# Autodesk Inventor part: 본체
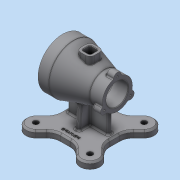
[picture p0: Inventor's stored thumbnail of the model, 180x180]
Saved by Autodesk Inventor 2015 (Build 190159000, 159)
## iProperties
Created: 2018-03
Part Number: 본체
Material: 일반
Document SubType Name: Modeling
Designer: SCD-A03
Density: 1 g/cm^3
Appearance: 기본값
Author: SCD-A03
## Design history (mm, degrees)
sketch "스케치1"
  geometry: L1 (50, 0)-(50, 45); L2 (50, 45)-(30, 45); L3 (30, 45)-(-27, 27.5); L4 (-50, 0)-(-50, 27.5); L5 (-27, 27.5)-(-50, 27.5); L6 (50, 0)-(-50, 0); L7 (0, 0)-(0, 7.405)
  constraints: 14 end point, 3 vertical, 2 horizontal, 1 perpendicular, 1 other
  dimensions: "d0" = 45 distance of L1.start L1.end; "d1" = 20 distance of L1.end L2.end; "d10" = 27.5 distance of L4.start L4.end; "d11" = 77 distance from line of L3.end L1; "d12" = 100 distance from line of L4.end L1; "d13" = 45 distance from line of L7.start L2; "d14" = 37.59532 distance from line of L7.end L2
revolve "회전1" sketch "스케치1" stored, may be unused: angle "d15" = 90 deg
node "작업 평면1"
sketch "스케치2"
  geometry: L1 (-19.544, 45)-(19.544, 45); L2 (45, 19.544)-(45, -19.544); L3 (-36.77, -36.77)-(-45, -45); L4 (-62.225, -36.77)-(-45, -19.544); L5 (19.544, 45)-(36.77, 62.225); L6 (-36.77, -62.225)-(-19.544, -45); L7 (45, 19.544)-(62.225, 36.77); L8 (45, 45)-(57.655, 57.655); L9 (-45, -45)-(-45, -32.068); L10 (-45, -19.544)-(-45, 19.544); L11 (-32.068, -45)-(-45, -45); L12 (62.225, -36.77)-(45, -19.544); L13 (-19.544, 45)-(-36.77, 62.225); L14 (45, -45)-(36.77, -36.77); L15 (-49.497, 49.497)-(-57.655, 57.655); L16 (36.77, -62.225)-(19.544, -45); L17 (-45, 19.544)-(-62.225, 36.77); L18 (-36.77, -36.77)-(-49.497, -49.497); L19 (-45, -45)-(-36.77, -36.77); L20 (45, -45)-(32.068, -45); L21 (19.544, -45)-(-19.544, -45); A1 r 18 centre (49.497, 49.497) between (62.225, 36.77) and (36.77, 62.225); A2 r 18 centre (49.497, -49.497) between (36.77, -62.225) and (62.225, -36.77); A3 r 18 centre (-49.497, 49.497) between (-36.77, 62.225) and (-62.225, 36.77); A4 r 18 centre (-49.497, -49.497) between (-62.225, -36.77) and (-36.77, -62.225); 1 further point
  constraints: 42 end point, 21 parallel, 8 point on circle, 4 centre point, 3 point on line, 1 coincident, 1 horizontal, 1 perpendicular
  dimensions: "d17" = 90 distance of L14.start L3.end; "d18" = 90 distance of L8.start L14.start; "d20" = 36 diameter of A1; "d25" = 36 diameter of A2
extrude "돌출1" join sketch "스케치2" distance "d28" = 12; taper "d29" = 0 deg
node "작업 평면2"
sketch "스케치3"
  geometry: L1 (-12.5, 12.5)-(12.5, 12.5); L2 (12.5, 12.5)-(12.5, -12.5); L3 (12.5, -12.5)-(-12.5, -12.5); L4 (-12.5, -12.5)-(-12.5, 12.5); L5 (-12.5, 12.5)-(12.5, -12.5); L6 (12.5, 12.5)-(-12.5, -12.5); 1 further point
  constraints: 12 end point, 2 midpoint, 2 parallel, 1 horizontal, 1 perpendicular
  dimensions: "d31" = 25 distance of L2.end L3.end; "d32" = 25 distance of L1.end L2.end
extrude "돌출2" join sketch "스케치3" stored distance "d33" = 12; taper "d34" = 0 deg
sketch "스케치4"
  geometry: L1 (-7.5, 7.5)-(7.5, 7.5); L2 (7.5, 7.5)-(7.5, -7.5); L3 (7.5, -7.5)-(-7.5, -7.5); L4 (-7.5, -7.5)-(-7.5, 7.5); L5 (-7.5, 7.5)-(7.5, -7.5); L6 (7.5, 7.5)-(-7.5, -7.5); 1 further point
  constraints: 12 end point, 2 midpoint, 2 parallel, 1 horizontal, 1 perpendicular
  dimensions: "d35" = 15 distance of L2.end L3.end; "d36" = 15 distance of L1.end L2.end
extrude "돌출3" cut sketch "스케치4" distance "d37" = 30; taper "d38" = 0 deg
sketch "스케치5"
  geometry: L1 (37, 4)-(-37, 4); L2 (-37, 4)-(-37, -4); L3 (-37, -4)-(37, -4); L4 (37, -4)-(37, 4); L5 (37, 4)-(-37, -4); L6 (-37, 4)-(37, -4); L7 (4, -24)-(-4, -24); L8 (-4, -24)-(-4, 24); L9 (-4, 24)-(4, 24); L10 (4, 24)-(4, -24); L11 (4, -24)-(-4, 24); L12 (-4, -24)-(4, 24); 1 further point
  constraints: 24 end point, 4 midpoint, 4 parallel, 2 horizontal, 2 perpendicular
  dimensions: "d39" = 8 distance of L8.end L9.end; "d40" = 8 distance of L3.end L1.start; "d41" = 74 distance of L2.end L3.end; "d42" = 48 distance of L9.end L7.start
extrude "돌출4" join sketch "스케치5" stored distance "d43" = 30; taper "d44" = 0 deg
sketch "스케치6"
  geometry: C1 r 7 at (-27.5, 0); 1 further point
  constraints: 1 centre point, 1 horizontal alignment, 1 other
  dimensions: "d46" = 14 diameter of C1
extrude "돌출5" join sketch "스케치6" distance "d47" = 15; taper "d48" = 0 deg
hole "구멍1" diameter "d54" = 3.242; stored, may be unused: countersink angle "d58" = 90 deg, drill point angle "d60" = 118 deg; dims "d52" = 10, "d53" = 10, "d55" = 9, "d56" = 4, "d57" = 2, "d59" = 11
sketch "스케치7"
  geometry: C1 r 45 at (0, 0) reference; 1 further point
  constraints: 1 horizontal alignment
  dimensions: "d64" = 40 distance of point (40, 0) C1.centre
hole "구멍2" sketch "스케치7" at (40, 0) diameter "d65" = 3.242; stored, may be unused: countersink angle "d69" = 90 deg, drill point angle "d71" = 118 deg; dims "d66" = 9, "d67" = 4, "d68" = 2, "d70" = 11
feature "면 기울기2" dims angle "d160" = 5 deg
hole "구멍3" diameter "d77" = 52; stored, may be unused: countersink angle "d81" = 90 deg, drill point angle "d83" = 0 deg; dims "d78" = 9, "d79" = 70, "d80" = 23, "d82" = 70, "d95" = 10, "d96" = 10
hole "구멍4" diameter "d88" = 40; stored, may be unused: countersink angle "d92" = 90 deg, drill point angle "d94" = 118 deg; dims "d86" = 10, "d87" = 10, "d89" = 9, "d90" = 70, "d91" = 23, "d93" = 70
hole "구멍5" diameter "d99" = 10; stored, may be unused: countersink angle "d103" = 90 deg, drill point angle "d105" = 118 deg; dims "d97" = 10, "d98" = 10, "d100" = 9, "d101" = 70, "d102" = 23, "d104" = 70
hole "구멍6" diameter "d108" = 10; stored, may be unused: countersink angle "d112" = 90 deg, drill point angle "d114" = 118 deg; dims "d106" = 10, "d107" = 10, "d109" = 9, "d110" = 70, "d111" = 23, "d113" = 70
hole "구멍7" diameter "d117" = 10; stored, may be unused: countersink angle "d121" = 90 deg, drill point angle "d123" = 118 deg; dims "d115" = 10, "d116" = 10, "d118" = 9, "d119" = 70, "d120" = 23, "d122" = 70
hole "구멍8" diameter "d126" = 10; stored, may be unused: countersink angle "d130" = 90 deg, drill point angle "d132" = 118 deg; dims "d124" = 10, "d125" = 10, "d127" = 9, "d128" = 70, "d129" = 23, "d131" = 70
sketch "스케치8"
  geometry: L1 (45, -19.544)-(45, 19.544) reference; 2 further points
  constraints: 1 other
  dimensions: "d133" = 35 distance of point (0, -35) point (0, 0); "d134" = 45 distance from line of point (0, -35) L1
feature "엠보싱1" sketch "스케치8" dims "d17" = 90, "d18" = 90, "d20" = 36, "d25" = 36, "d135" = 0.5, "d136" = 0
fillet "모깎기1" dims "d137" = 25
fillet "모깎기3" dims "d139" = 8
fillet "모깎기4" dims "d140" = 1
chamfer "모따기1" distance "d141" = 3; stored, may be unused: second distance "d142" = 2, angle "d143" = 45 deg
fillet "모깎기5" dims "d144" = 3
fillet "모깎기6" dims "d145" = 3
fillet "모깎기7" dims "d146" = 3
fillet "모깎기8" dims "d147" = 3
fillet "모깎기9" dims "d148" = 1
fillet "모깎기10" dims "d149" = 3
fillet "모깎기11" dims "d150" = 3
chamfer "모따기2" distance "d151" = 1; stored, may be unused: second distance "d152" = 2, angle "d153" = 45 deg
chamfer "모따기3" distance "d154" = 1; stored, may be unused: second distance "d155" = 2, angle "d156" = 45 deg
fillet "모깎기12" dims "d157" = 3
fillet "모깎기13" dims "d158" = 3
fillet "모깎기14" dims "d159" = 3
node "솔리드1"
pattern_circular "원형 패턴1" dims angle "d50" = 360 deg
pattern_circular "원형 패턴2" dims angle "d62" = 360 deg
pattern_circular "원형 패턴3" dims angle "d73" = 360 deg
other parameters: "d16" = -82, "d21" = 18, "d22" = 18, "d23" = 36, "d24" = 36, "d26" = 18, "d27" = 18, "d30" = 45
